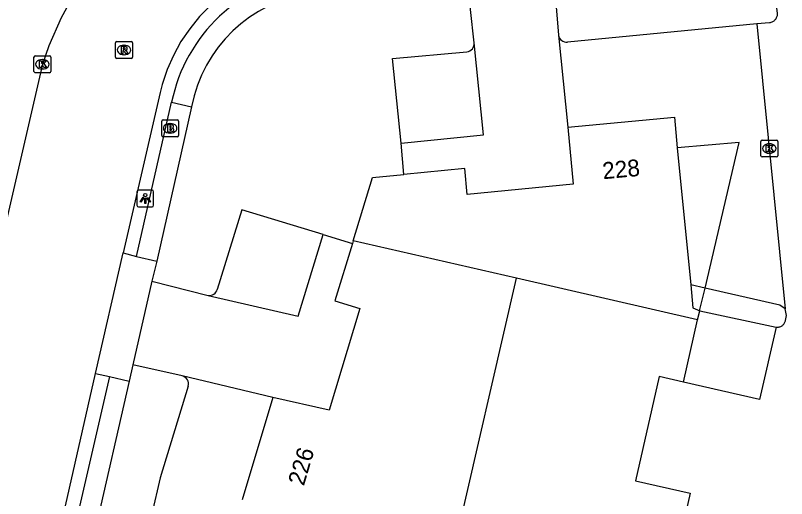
# Model space of a CAD drawing. Extents: x 161389 to 162585, y 388479 to 389761.
# Drawn here: x 162401.19 to 162447.01, y 389058.37 to 389087.1 of the extents above; entities that cross this region are included whole.
import ezdxf

# ---------------------------------------------------------------- set-up
doc = ezdxf.new("R2010")
doc.units = 0
for name, color, linetype in [('IMGEO_Brandkraan', 7, 'Continuous'), ('IMGEO_Kolk', 7, 'Continuous'), ('IMGEO_Lichtpunt', 7, 'Continuous'), ('IMGEO_Pand', 7, 'Continuous'), ('IMGEO_Pand_nummerreeks', 7, 'Continuous'), ('IMGEO_Pand_overbouw', 7, 'Continuous'), ('IMGEO_Parkeervlak_open', 7, 'Continuous'), ('IMGEO_Rijbaan_lokaal_gesloten', 7, 'Continuous'), ('IMGEO_Rijbaan_lokaal_open', 7, 'Continuous'), ('IMGEO_Rioolput', 7, 'Continuous'), ('IMGEO_Voetpad_open', 7, 'Continuous')]:
    doc.layers.add(name, color=color, linetype=linetype)

msp = doc.modelspace()

# ---------------------------------------------------------------- linework, layer by layer
at = {"layer": 'IMGEO_Brandkraan'}
for p, q in [((162409.958, 389080.886), (162410.81, 389080.886)), ((162409.883, 389079.96), (162409.883, 389080.812)), ((162410.371, 389080.666), (162410.396, 389080.666)), ((162410.884, 389080.812), (162410.884, 389079.96)), ((162410.394, 389080.106), (162410.369, 389080.106)), ((162410.81, 389079.886), (162409.958, 389079.886))]:
    msp.add_line(p, q, dxfattribs=at)
for points in [[(162409.958, 389080.886), (162410.81, 389080.886)], [(162409.883, 389079.96), (162409.883, 389080.812)], [(162410.231, 389080.586), (162410.231, 389080.186), (162410.444, 389080.186)], [(162410.462, 389080.586), (162410.231, 389080.586)], [(162410.41, 389080.505), (162410.356, 389080.505), (162410.356, 389080.429)], [(162410.356, 389080.429), (162410.409, 389080.429)], [(162410.884, 389080.812), (162410.884, 389079.96)], [(162410.418, 389080.353), (162410.356, 389080.353), (162410.356, 389080.272)], [(162410.356, 389080.272), (162410.418, 389080.272)], [(162410.81, 389079.886), (162409.958, 389079.886)]]:
    msp.add_lwpolyline(points, dxfattribs=at)
for centre, radius, start, end in [((162409.96, 389080.81), 0.0765, 91.552, 178.448), ((162409.96, 389080.81), 0.0765, 91.552, 178.448), ((162410.808, 389080.81), 0.0765, 1.552, 88.448), ((162410.808, 389080.81), 0.0765, 1.552, 88.448), ((162410.411, 389080.467), 0.0379, 267.8285, 90.9355), ((162410.466, 389080.441), 0.145, 59.4692, 91.5367), ((162410.491, 389080.488), 0.0922, 285.5137, 58.1501), ((162410.496, 389080.296), 0.105, 301.3115, 78.989), ((162409.96, 389079.962), 0.0765, 181.552, 268.448), ((162409.96, 389079.962), 0.0765, 181.552, 268.448), ((162410.419, 389080.312), 0.0404, 269.8759, 90.5077), ((162410.45, 389080.437), 0.251, 268.6676, 293.5347), ((162410.808, 389079.962), 0.0765, 271.552, 358.448), ((162410.808, 389079.962), 0.0765, 271.552, 358.448)]:
    msp.add_arc(centre, radius, start, end, dxfattribs=at)
for centre, major_axis, ratio, start_param, end_param in [((162410.37, 389080.386), (-0.387, 0.002), 0.722429, 4.712389, 7.853982), ((162410.395, 389080.386), (-0.39, 0.002), 0.717154, 1.570796, 4.712389)]:
    msp.add_ellipse(centre, major_axis=major_axis, ratio=ratio, start_param=start_param, end_param=end_param, dxfattribs=at)
at = {"layer": 'IMGEO_Kolk'}
for p, q in [((162402.291, 389083.766), (162402.291, 389084.618)), ((162402.366, 389084.692), (162403.218, 389084.692)), ((162403.292, 389084.618), (162403.292, 389083.766)), ((162402.779, 389084.472), (162402.804, 389084.472)), ((162403.218, 389083.692), (162402.366, 389083.692)), ((162402.802, 389083.912), (162402.777, 389083.912)), ((162445.479, 389078.758), (162445.479, 389079.61)), ((162445.554, 389079.684), (162446.406, 389079.684)), ((162445.967, 389079.464), (162445.992, 389079.464)), ((162446.48, 389079.61), (162446.48, 389078.758)), ((162446.406, 389078.684), (162445.554, 389078.684)), ((162445.99, 389078.904), (162445.965, 389078.904))]:
    msp.add_line(p, q, dxfattribs=at)
for points in [[(162402.291, 389083.766), (162402.291, 389084.618)], [(162402.366, 389084.692), (162403.218, 389084.692)], [(162403.292, 389084.618), (162403.292, 389083.766)], [(162402.612, 389084.392), (162402.735, 389084.392), (162402.735, 389084.241), (162402.865, 389084.392), (162403.029, 389084.392), (162402.883, 389084.241), (162403.036, 389083.992), (162402.884, 389083.992), (162402.799, 389084.156), (162402.735, 389084.089), (162402.735, 389083.992), (162402.612, 389083.992), (162402.612, 389084.392)], [(162403.218, 389083.692), (162402.366, 389083.692)], [(162445.479, 389078.758), (162445.479, 389079.61)], [(162445.554, 389079.684), (162446.406, 389079.684)], [(162446.48, 389079.61), (162446.48, 389078.758)], [(162445.8, 389079.384), (162445.923, 389079.384), (162445.923, 389079.233), (162446.053, 389079.384), (162446.217, 389079.384), (162446.071, 389079.233), (162446.224, 389078.984), (162446.072, 389078.984), (162445.987, 389079.148), (162445.923, 389079.081), (162445.923, 389078.984), (162445.8, 389078.984), (162445.8, 389079.384)], [(162446.406, 389078.684), (162445.554, 389078.684)]]:
    msp.add_lwpolyline(points, dxfattribs=at)
for centre, start, end in [((162402.368, 389084.616), 91.552, 178.448), ((162402.368, 389084.616), 91.552, 178.448), ((162403.216, 389084.616), 1.552, 88.448), ((162403.216, 389084.616), 1.552, 88.448), ((162402.368, 389083.768), 181.552, 268.448), ((162402.368, 389083.768), 181.552, 268.448), ((162403.216, 389083.768), 271.552, 358.448), ((162403.216, 389083.768), 271.552, 358.448), ((162445.556, 389079.608), 91.552, 178.448), ((162445.556, 389079.608), 91.552, 178.448), ((162446.404, 389079.608), 1.552, 88.448), ((162446.404, 389079.608), 1.552, 88.448), ((162445.556, 389078.76), 181.552, 268.448), ((162445.556, 389078.76), 181.552, 268.448), ((162446.404, 389078.76), 271.552, 358.448), ((162446.404, 389078.76), 271.552, 358.448)]:
    msp.add_arc(centre, 0.0765, start, end, dxfattribs=at)
for centre, major_axis, ratio, start_param, end_param in [((162402.778, 389084.192), (-0.387, 0.002), 0.722429, 4.712389, 7.853982), ((162402.803, 389084.192), (-0.39, 0.002), 0.717154, 1.570796, 4.712389), ((162445.966, 389079.184), (-0.387, 0.002), 0.722429, 4.712389, 7.853982), ((162445.991, 389079.184), (-0.39, 0.002), 0.717154, 1.570796, 4.712389)]:
    msp.add_ellipse(centre, major_axis=major_axis, ratio=ratio, start_param=start_param, end_param=end_param, dxfattribs=at)
at = {"layer": 'IMGEO_Lichtpunt'}
for p, q in [((162409.308, 389076.714), (162408.5, 389076.714)), ((162409.308, 389076.714), (162408.5, 389076.714)), ((162408.406, 389076.619), (162408.406, 389075.812)), ((162408.406, 389076.619), (162408.406, 389075.812)), ((162409.402, 389075.812), (162409.402, 389076.619)), ((162409.402, 389075.812), (162409.402, 389076.619)), ((162408.5, 389075.718), (162409.308, 389075.718)), ((162408.5, 389075.718), (162409.308, 389075.718))]:
    msp.add_line(p, q, dxfattribs=at)
for points in [[(162408.78, 389076.283), (162408.819, 389076.255), (162408.631, 389075.993), (162408.593, 389076.02), (162408.78, 389076.283)], [(162408.992, 389076.255), (162409.03, 389076.282), (162409.217, 389076.02), (162409.178, 389075.992), (162408.992, 389076.255)], [(162408.882, 389076.235), (162408.929, 389076.235), (162408.929, 389075.913), (162408.882, 389075.913), (162408.882, 389076.235)]]:
    msp.add_lwpolyline(points, dxfattribs=at)
msp.add_circle((162408.905, 389076.417), 0.0994, dxfattribs=at)
for centre, start, end in [((162408.5, 389076.619), 90, 180), ((162408.5, 389076.619), 90, 180), ((162409.308, 389076.619), 0, 90), ((162409.308, 389076.619), 0, 90), ((162408.5, 389075.812), 180, 270), ((162408.5, 389075.812), 180, 270), ((162409.308, 389075.812), 270, 0), ((162409.308, 389075.812), 270, 360)]:
    msp.add_arc(centre, 0.0946, start, end, dxfattribs=at)
at = {"layer": 'IMGEO_Pand'}
for points in [[(162434.003, 389080.452), (162440.341, 389081.046), (162440.515, 389079.22), (162441.309, 389071.082)], [(162434.003, 389080.452), (162434.322, 389077.056), (162428.037, 389076.445), (162427.889, 389077.988), (162424.258, 389077.639)], [(162421.258, 389073.699), (162422.405, 389077.461), (162424.258, 389077.639)], [(162421.207, 389073.532), (162420.168, 389070.124), (162421.651, 389069.672), (162419.821, 389063.627), (162416.475, 389064.387)], [(162421.258, 389073.699), (162421.207, 389073.532)], [(162430.953, 389071.472), (162421.258, 389073.699)], [(162427.262, 389055.385), (162430.953, 389071.472)], [(162441.723, 389068.999), (162430.953, 389071.472)], [(162441.309, 389071.082), (162441.443, 389069.705), (162441.846, 389069.535)], [(162441.723, 389068.999), (162441.846, 389069.535)], [(162440.879, 389065.304), (162441.723, 389068.999)], [(162440.879, 389065.304), (162439.436, 389065.633), (162438.022, 389059.422), (162441.269, 389058.686), (162439.865, 389052.482), (162438.025, 389052.885)], [(162416.475, 389064.387), (162414.667, 389058.292)]]:
    msp.add_lwpolyline(points, dxfattribs=at)
at = {"layer": 'IMGEO_Pand_overbouw'}
msp.add_lwpolyline([(162441.846, 389069.535), (162441.863, 389069.609), (162442.164, 389070.888), (162444.197, 389079.539), (162440.515, 389079.22), (162441.309, 389071.082), (162441.443, 389069.705)], close=True, dxfattribs=at)
at = {"layer": 'IMGEO_Parkeervlak_open'}
for points in [[(162445.239, 389086.59), (162433.997, 389085.498)], [(162424.103, 389079.494), (162423.596, 389084.537), (162428.013, 389084.927)], [(162419.48, 389074.076), (162414.64, 389075.54), (162413.178, 389070.805)], [(162446.923, 389069.652), (162446.603, 389069.881), (162442.164, 389070.888), (162441.309, 389071.082)], [(162441.846, 389069.535), (162446.392, 389068.57)], [(162411.462, 389065.055), (162409.797, 389059.603), (162408.807, 389055.329)]]:
    msp.add_lwpolyline(points, dxfattribs=at)
for centre, radius, start, end in [((162433.962, 389086.003), 0.506, 188.515, 274.0091), ((162427.938, 389085.436), 0.514, 278.3653, 4.5696), ((162412.725, 389070.916), 0.467, 260.2936, 346.2374), ((162410.974, 389065.175), 0.503, 346.1616, 75.7936)]:
    msp.add_arc(centre, radius, start, end, dxfattribs=at)
at = {"layer": 'IMGEO_Rijbaan_lokaal_gesloten'}
for points in [[(162408.163, 389092.728), (162406.907, 389091.431), (162405.772, 389090.027), (162404.767, 389088.528), (162403.9, 389086.945), (162403.178, 389085.29), (162402.792, 389084.192), (162400.663, 389074.932), (162399.481, 389069.789)], [(162426.478, 389091.313), (162418.563, 389090.42), (162417.648, 389090.261), (162416.751, 389090.021), (162415.879, 389089.701), (162415.039, 389089.305), (162414.238, 389088.836), (162413.482, 389088.297), (162412.777, 389087.692), (162412.129, 389087.027), (162411.543, 389086.307), (162411.024, 389085.537), (162410.575, 389084.724), (162410.201, 389083.874), (162409.904, 389082.994), (162409.78, 389082.521), (162407.598, 389072.984)], [(162405.954, 389065.801), (162407.598, 389072.984)], [(162403.957, 389057.076), (162405.954, 389065.801)]]:
    msp.add_lwpolyline(points, dxfattribs=at)
at = {"layer": 'IMGEO_Rijbaan_lokaal_open'}
for points in [[(162446.006, 389090.713), (162446.086, 389090.21), (162446.445, 389087.22), (162446.447, 389087.174), (162446.444, 389087.126), (162446.438, 389087.079), (162446.427, 389087.033), (162446.412, 389086.988), (162446.393, 389086.945), (162446.37, 389086.903), (162446.344, 389086.863), (162446.314, 389086.826), (162446.281, 389086.792), (162446.245, 389086.761), (162446.207, 389086.733), (162446.166, 389086.709), (162446.123, 389086.689), (162446.079, 389086.672), (162446.033, 389086.659), (162445.986, 389086.651), (162445.239, 389086.59)], [(162433.112, 389090.025), (162433.461, 389085.928)], [(162428.451, 389085.477), (162428.004, 389089.451)], [(162445.239, 389086.59), (162446.923, 389069.652)], [(162433.461, 389085.928), (162434.003, 389080.452)], [(162424.103, 389079.494), (162429.004, 389079.989), (162428.451, 389085.477)], [(162424.258, 389077.639), (162424.103, 389079.494)], [(162412.646, 389070.456), (162417.994, 389069.218), (162419.48, 389074.076)], [(162419.48, 389074.076), (162421.207, 389073.532)], [(162409.297, 389071.306), (162408.159, 389066.317)], [(162409.297, 389071.306), (162412.646, 389070.456)], [(162446.392, 389068.57), (162446.437, 389068.566), (162446.482, 389068.567), (162446.527, 389068.572), (162446.572, 389068.58), (162446.615, 389068.593), (162446.657, 389068.609), (162446.698, 389068.629), (162446.736, 389068.653), (162446.773, 389068.679), (162446.806, 389068.71), (162446.837, 389068.742), (162446.865, 389068.778), (162446.89, 389068.816), (162446.911, 389068.856), (162446.928, 389068.898), (162446.942, 389068.941), (162446.948, 389068.966), (162447.007, 389069.254), (162446.923, 389069.652)], [(162446.392, 389068.57), (162445.404, 389064.269), (162440.879, 389065.304)], [(162411.097, 389065.663), (162408.159, 389066.317)], [(162416.475, 389064.387), (162411.097, 389065.663)]]:
    msp.add_lwpolyline(points, dxfattribs=at)
at = {"layer": 'IMGEO_Rioolput'}
for p, q in [((162407.138, 389084.617), (162407.138, 389085.469)), ((162407.213, 389085.543), (162408.065, 389085.543)), ((162408.139, 389085.469), (162408.139, 389084.617)), ((162407.626, 389085.323), (162407.651, 389085.323)), ((162408.065, 389084.543), (162407.213, 389084.543)), ((162407.649, 389084.763), (162407.624, 389084.763))]:
    msp.add_line(p, q, dxfattribs=at)
for points in [[(162407.138, 389084.617), (162407.138, 389085.469)], [(162407.213, 389085.543), (162408.065, 389085.543)], [(162408.139, 389085.469), (162408.139, 389084.617)], [(162407.727, 389085.241), (162407.475, 389085.243), (162407.475, 389084.843)], [(162407.475, 389084.843), (162407.599, 389084.843), (162407.599, 389085.005), (162407.61, 389085.005)], [(162407.653, 389085.162), (162407.599, 389085.162), (162407.599, 389085.081)], [(162407.599, 389085.081), (162407.651, 389085.081)], [(162407.657, 389084.976), (162407.728, 389084.843), (162407.868, 389084.843), (162407.803, 389084.969)], [(162408.065, 389084.543), (162407.213, 389084.543)]]:
    msp.add_lwpolyline(points, dxfattribs=at)
for centre, radius, start, end in [((162407.215, 389085.467), 0.0765, 91.552, 178.448), ((162407.215, 389085.467), 0.0765, 91.552, 178.448), ((162408.063, 389085.467), 0.0765, 1.552, 88.448), ((162408.063, 389085.467), 0.0765, 1.552, 88.448), ((162407.609, 389084.952), 0.0533, 26.0293, 88.6989), ((162407.635, 389085.27), 0.19, 274.7715, 282.9687), ((162407.659, 389085.066), 0.0964, 77.0061, 93.1865), ((162407.673, 389085.123), 0.0378, 276.6634, 79.6772), ((162407.726, 389085.131), 0.109, 350.3612, 89.416), ((162407.724, 389085.131), 0.112, 277.5842, 350.9817), ((162407.708, 389084.916), 0.108, 29.5134, 73.7905), ((162407.215, 389084.619), 0.0765, 181.552, 268.448), ((162407.215, 389084.619), 0.0765, 181.552, 268.448), ((162408.063, 389084.619), 0.0765, 271.552, 358.448), ((162408.063, 389084.619), 0.0765, 271.552, 358.448)]:
    msp.add_arc(centre, radius, start, end, dxfattribs=at)
for centre, major_axis, ratio, start_param, end_param in [((162407.625, 389085.043), (-0.387, 0.002), 0.722429, 4.712389, 7.853982), ((162407.65, 389085.043), (-0.39, 0.002), 0.717154, 1.570796, 4.712389)]:
    msp.add_ellipse(centre, major_axis=major_axis, ratio=ratio, start_param=start_param, end_param=end_param, dxfattribs=at)
at = {"layer": 'IMGEO_Voetpad_open'}
for points in [[(162408.38, 389072.764), (162410.47, 389081.934)], [(162410.47, 389081.934), (162411.656, 389081.657)], [(162411.656, 389081.657), (162409.582, 389072.482)], [(162407.598, 389072.984), (162408.38, 389072.764)], [(162408.38, 389072.764), (162409.582, 389072.482)], [(162409.582, 389072.482), (162409.297, 389071.306)], [(162408.159, 389066.317), (162407.946, 389065.363)], [(162405.954, 389065.801), (162406.77, 389065.64)], [(162406.77, 389065.64), (162404.763, 389056.881)], [(162407.946, 389065.363), (162405.95, 389056.6)], [(162406.77, 389065.64), (162407.946, 389065.363)]]:
    msp.add_lwpolyline(points, dxfattribs=at)
for centre, radius, start, end in [((162419.935, 389080.009), 9.659, 97.944, 168.5041), ((162419.88, 389080.12), 8.367, 97.9226, 169.4164)]:
    msp.add_arc(centre, radius, start, end, dxfattribs=at)

# ---------------------------------------------------------------- texts
at = {"layer": 'IMGEO_Pand_nummerreeks'}
for s, rotation, p in [('228', 5.3541, (162436.109, 389077.355)), ('226', 73.4777, (162418.323, 389059.085))]:
    msp.add_text(s, height=1, rotation=rotation, dxfattribs=at).set_placement(p)

doc.saveas('drawing.dxf')
